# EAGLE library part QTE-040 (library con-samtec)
0,8mm HI-SPEED HEADER QTE Series Source: http://www.samtec.com/ftppub/pdf/QTE.PDF http://www.samtec.com/ftppub/cpdf/QTE-XXX-XX-X-D-XXX-FOOTPRINT.pdf
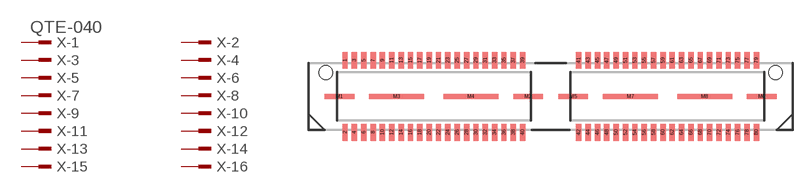
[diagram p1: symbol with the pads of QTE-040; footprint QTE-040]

Designator prefix X; gates -1=MPINV -2=MPIN -3=MPIN -4=MPIN -5=MPIN -6=MPIN -7=MPIN -8=MPIN -9=MPIN -10=MPIN -11=MPIN -12=MPIN -13=MPIN -14=MPIN -15=MPIN -16=MPIN -17=MPIN -18=MPIN -19=MPIN -20=MPIN -21=MPIN -22=MPIN -23=MPIN -24=MPIN -25=MPIN -26=MPIN -27=MPIN -28=MPIN -29=MPIN -30=MPIN -31=MPIN -32=MPIN -33=MPIN -34=MPIN -35=MPIN -36=MPIN -37=MPIN -38=MPIN -39=MPIN -40=MPIN -41=MPIN -42=MPIN -43=MPIN -44=MPIN -45=MPIN -46=MPIN -47=MPIN -48=MPIN -49=MPIN -50=MPIN -51=MPIN -52=MPIN -53=MPIN -54=MPIN -55=MPIN -56=MPIN -57=MPIN -58=MPIN -59=MPIN -60=MPIN -61=MPIN -62=MPIN -63=MPIN -64=MPIN -65=MPIN -66=MPIN -67=MPIN -68=MPIN -69=MPIN -70=MPIN -71=MPIN -72=MPIN -73=MPIN -74=MPIN -75=MPIN -76=MPIN -77=MPIN -78=MPIN -79=MPIN -80=MPIN

## QTE-040 (OC_FARNELL: unknown; OC_NEWARK: unknown)  [QTE-040]
1  -1:1  pas
2  -2:1  pas
3  -3:1  pas
4  -4:1  pas
5  -5:1  pas
6  -6:1  pas
7  -7:1  pas
8  -8:1  pas
9  -9:1  pas
10  -10:1  pas
11  -11:1  pas
12  -12:1  pas
13  -13:1  pas
14  -14:1  pas
15  -15:1  pas
16  -16:1  pas
17  -17:1  pas
18  -18:1  pas
19  -19:1  pas
20  -20:1  pas
21  -21:1  pas
22  -22:1  pas
23  -23:1  pas
24  -24:1  pas
25  -25:1  pas
26  -26:1  pas
27  -27:1  pas
28  -28:1  pas
29  -29:1  pas
30  -30:1  pas
31  -31:1  pas
32  -32:1  pas
33  -33:1  pas
34  -34:1  pas
35  -35:1  pas
36  -36:1  pas
37  -37:1  pas
38  -38:1  pas
39  -39:1  pas
40  -40:1  pas
41  -41:1  pas
42  -42:1  pas
43  -43:1  pas
44  -44:1  pas
45  -45:1  pas
46  -46:1  pas
47  -47:1  pas
48  -48:1  pas
49  -49:1  pas
50  -50:1  pas
51  -51:1  pas
52  -52:1  pas
53  -53:1  pas
54  -54:1  pas
55  -55:1  pas
56  -56:1  pas
57  -57:1  pas
58  -58:1  pas
59  -59:1  pas
60  -60:1  pas
61  -61:1  pas
62  -62:1  pas
63  -63:1  pas
64  -64:1  pas
65  -65:1  pas
66  -66:1  pas
67  -67:1  pas
68  -68:1  pas
69  -69:1  pas
70  -70:1  pas
71  -71:1  pas
72  -72:1  pas
73  -73:1  pas
74  -74:1  pas
75  -75:1  pas
76  -76:1  pas
77  -77:1  pas
78  -78:1  pas
79  -79:1  pas
80  -80:1  pas

## Footprint QTE-040 (pad centres in mm)
0,8mm HI-SPEED HEADER QTE Series Source: http://www.samtec.com/ftppub/pdf/QTE.PDF http://www.samtec.com/ftppub/cpdf/QTE-XXX-XX-X-D-XXX-FOOTPRINT.pdf
smd 0.46 x 1.45: 1 -17.595,3.09; 2 -17.595,-3.08; 3 -16.795,3.09; 4 -16.795,-3.08; 5 -15.995,3.09; 6 -15.995,-3.08; 7 -15.195,3.09; 8 -15.195,-3.08; 9 -14.395,3.09; 10 -14.395,-3.08; 11 -13.595,3.09; 12 -13.595,-3.08; 13 -12.795,3.09; 14 -12.795,-3.08; 15 -11.995,3.09; 16 -11.995,-3.08; 17 -11.195,3.09; 18 -11.195,-3.08; 19 -10.395,3.09; 20 -10.395,-3.08; 21 -9.595,3.09; 22 -9.595,-3.08; 23 -8.795,3.09; 24 -8.795,-3.08; 25 -7.995,3.09; 26 -7.995,-3.08; 27 -7.195,3.09; 28 -7.195,-3.08; 29 -6.395,3.09; 30 -6.395,-3.08; 31 -5.595,3.09; 32 -5.595,-3.08; 33 -4.795,3.09; 34 -4.795,-3.08; 35 -3.995,3.09; 36 -3.995,-3.08; 37 -3.195,3.09; 38 -3.195,-3.08; 39 -2.395,3.09; 40 -2.395,-3.08; 41 2.405,3.09; 42 2.405,-3.08; 43 3.205,3.09; 44 3.205,-3.08; 45 4.005,3.09; 46 4.005,-3.08; 47 4.805,3.09; 48 4.805,-3.08; 49 5.605,3.09; 50 5.605,-3.08; 51 6.405,3.09; 52 6.405,-3.08; 53 7.205,3.09; 54 7.205,-3.08; 55 8.005,3.09; 56 8.005,-3.08; 57 8.805,3.09; 58 8.805,-3.08; 59 9.605,3.09; 60 9.605,-3.08; 61 10.405,3.09; 62 10.405,-3.08; 63 11.205,3.09; 64 11.205,-3.08; 65 12.005,3.09; 66 12.005,-3.08; 67 12.805,3.09; 68 12.805,-3.08; 69 13.605,3.09; 70 13.605,-3.08; 71 14.405,3.09; 72 14.405,-3.08; 73 15.205,3.09; 74 15.205,-3.08; 75 16.005,3.09; 76 16.005,-3.08; 77 16.805,3.09; 78 16.805,-3.08; 79 17.605,3.09; 80 17.605,-3.08
smd 2.54 x 0.43: M1 -18.065,0; M2 -1.935,0; M5 1.935,0; M6 18.065,0
smd 4.7 x 0.43: M3 -13.175,0; M4 -6.825,0; M7 6.825,0; M8 13.175,0
hole 1.19 at -19.24,2.04
hole 1.19 at 19.24,2.04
